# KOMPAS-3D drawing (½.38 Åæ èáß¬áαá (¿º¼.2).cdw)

Views: Вид 1, Вид 2
Referenced files in C:\Program Files\ASCON\KOMPAS-3D V10\Sys\: SPDS.lcs
Referenced files: План ПС Сазоново.cdw
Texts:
  Ирина
  Текст на чертеже
  Размерные надписи
  Шероховатость
  Линия-выноска #1
  Линия-выноска #2
  Линия-выноска #3
  Отклонения формы и база
  Заголовок таблицы
  Ячейка таблицы
  Стрелка вида
  Обозначение изменения
  Фигурная скобка
  Номер узла
  Марка координационной оси
  VRCB
  Выносная надпись
  Обозначение узла
  Марка/позиционное обозначение с линией-выноской
  Марка/позиционное обозначение на линии
  Марка/позиционное обозначение без линии-выноски
  Normal
  Лит-Масса-Масштаб
  Материал-Предприятие
  Title Specification
  Body Specification ( left align )
  Body Specificaton ( centered )
  Без имени
  heading 1
  Знак Знак Знак Знак Знак Знак
  Verdana
  Body Text
  MS Sans Serif
  Txt
  Simplex
  TXT
  Обычный
  Термин
  Список определений
  Адрес
  Цитаты
  Форматированный
  Courier New
  Z-конец формы
  Z-начало формы
  Additional DXF text style 0
  Абзац Знак
  Body Text 3
  Title
  ТекстШаг1
  Шрифт 2.5
  Заголовки
  txt
  heading 2
  AGOpus
  footer
  Денис
  RUSTXT
  Обычный (веб)
  ООббыыччнныыйй
  Definition Term
  Definition List
  Address
  Blockquote
  Preformatted
  z-Bottom of Form
  z-Top of Form
  header
  NormalParagraphStyle
  ссылки
  Подпись в квадратике
  табл
  цепи
  Маркировка
  клеммы, контакты
  тексты табл
  Тексты. 3,2
  ЗОНА_привяз
  текст переноса
  ТТееррммиинн
  ССппииссоокк ооппррееддееллеенниийй
  ААддрреесс
  ЦЦииттааттыы
  ФФооррммааттиирроовваанннныыйй
  Z-ккооннеецц ффооррммыы
  Z-ннааччааллоо ффооррммыы
  GOST 2.304 type A
  rustxt
  heading 8
  heading 3
  heading 6
  heading 7
  russ
  heading 4
  heading 5
  heading 9
  HeliosLight
  Pa3
  Pa1
  Три с половиной
  style2
  Table Contents
  Table Heading
  ГОСТ_МНЕ
  ESK - Обозначение
  маркировка
  ISOCP
  ROMANS
  SIMPLEX
  Текст 3,5
  Tahoma
  CNBNDG+TimesNewRoman
  Subtitle
  FR5
  romanc
  eskd1
  Pa15
  Pa18
  Аппараты
  подписи
  Состав чартежа
  ячейка табл.
  Ссылки
  Пояснения
  Клеммник текст
  CM12
  romans
  gif
  Пояснения 2
  текст табл
  ISOCPEUR
  CC С?т?и?л?ь? П?о? ц?е?н?т?р?у?
  SignaColumn-Light
  Cambria
  Normal (Web)
  Подписи
  Ошиновка
  Демонтаж
  кабельные конструкции
  Примечания:
  1. Для нужд строительства (размещение задействованного в строительстве персонала, обеспечение
  электроэнергией) использовать временные мобильные инвентарные здания;
  2. При выполнении всех строительно-монтажных работ на площадке необходимо руководствоваться
  требованиями СНиП 12-03-2001 "Безопасность труда в строительстве. Общие требования",
  СНиП 12-04-2002 "Безопасность труда в строительстве. Строительное производство", а также
  ПОТ-РМ-016-2001/РД 153-34.0-03.150-00 "Межотраслевые правила по охране труда (правила
  безопасности) при эксплуатации электроустановок";
  3. Наружное освещение строительной площадки осуществляется за счет существующего освещения;
  4. Под временные сооружения (поз. II, III и IV) устраивается площадка из дорожных плит ПД 60-20 на
  щебеночном основании толщиной 15см;
  5. На период строительства для электроснабжения временных зданий и сооружений использовать ди-
  зельную электростанцию. Прокладку  кабеля от дизельной электростанции до вагончиков выполнить
  в воздушном исполнении в гофрированной трубе диаметром 30 мм, на вагончиках кабель закрепить
  скобами. Щиток временного электроснабжения навесить на стенку вагона-дома для отдыха рабочих;
  6. При выполнении монтажных работ использовать инвентарные лестницы и леса;
  7. Тонкой линией изображено существующее оборудование, замена которого проектом не предусматри-
  вается, утолщенной - вновь устанавливаемое оборудование.
  8. Условные обозначения см. 16/01-ПОД,л.1.
  9. Грузовысотные характеристики КМУ ИНМАН ИМ-150 см. 16/01-ПОС,л.7.
  Экспликация зданий и сооружений
  Номер
  на плане
  Постоянные здания и сооружения
  ОПУ
  Существующее
  ЗРУ-10 кВ
  Трансформатор 1Т, маслоприемник
  Существующий
  Трансформатор 2Т, маслоприемник
  Временные здания и сооружения
  III
  Вагон-дом для кратковременного отдых рабочих
  Уборная
  Дизельная электростанция
  Контейнеры для ТБО (0,75м 3 ) и жидких хоз.-быт.стоков(1м 3 )
  «Екатерина» 9,0х3,0
  Туалетная кабина "Люкс"
  ОАО ПКТИпромстрой
  КМУ ИНМАН ИМ-150
  POLYLINE_STYLE_0.25_RGB_128_64_0
  POLYLINE_STYLE_0.18_RGB_0_0_0
  POLYLINE_STYLE_0.20_RGB_0_0_0
  POLYLINE_STYLE_0.18_RGB_0_80_80
  Стили документа
  Бортовой автомобиль КамАЗ 43114-027-02
  АТ ППР#010#0104
  Перезавод ВЛ на ПС Тюмень. Реконструкция устройств
  РЗ и ПА на обратных концах отходящих ВЛ,
  ВОЛС Тюменского ТПО
  Политова
  Разраб.
  Микрюков
  Строительный генеральный план
  ПС 110/10 кВ Каскара
  Ведомость эскизного проекта
  Нов.
  ГИП
  Матвеев
  Ромин
Dimensions and other numbers on the sheet: 16/01-ПОД; 7; 2,5; 1,8; 2.5; 3,2_; 3.5; 3,2; 2,5 (контакты, клеммы); 3,2 (надписи); 3,2 (Зоны); 5; 2,5_01; 2,5_3; 3,5_01; 3,5_tabl; 5_заголовок; 2,3_; 3,2_зона не привяз; 3,5; 3.2 маркировка; 3,2 элементы; 3,2 линия; 3,2 таблица; 2,5 грязносинь; 2.5 курсив; 2.5_Э5_надписи; 2.5_Э5_ссылки; 2.5_кабель; 3.2; 2.5 надписи; 3 и 5; 5,0_белый_подчёркнутый; 3.2 фиол; 3.2 (текст); 1; 2; 3; 4; 10,6; 05.14; 38; 254-14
